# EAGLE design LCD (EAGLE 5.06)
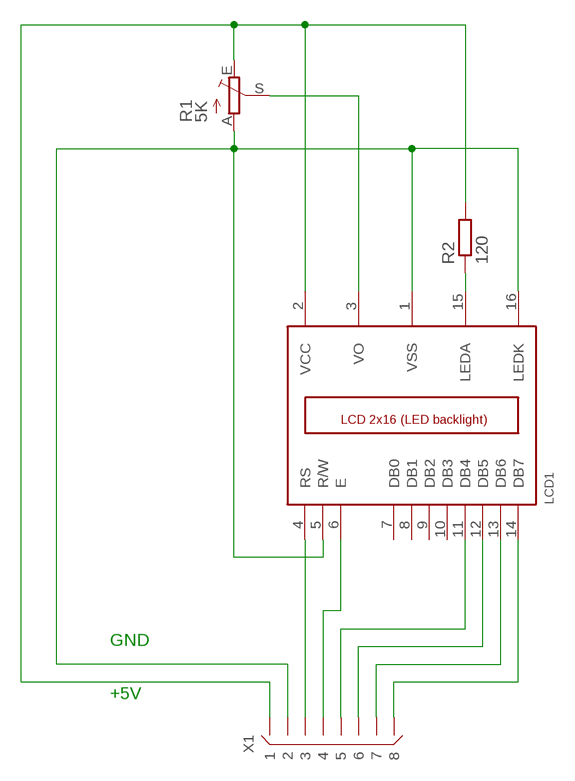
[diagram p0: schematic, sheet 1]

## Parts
LCD1  LCD_2X16  [HY-1602F]
R1  5K  TRIM_EU-CA6V  [CA6V]
R2  120  R-EU_0207/10  [0207/10]
X1  X08L  [X08L-SIL]

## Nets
N$1: LCD1.11(DB4) X1.5
N$2: LCD1.2(VCC) R1.E R2.2 X1.1
N$3: LCD1.3(VO) R1.S
N$4: LCD1.12(DB5) X1.6
N$5: LCD1.13(DB6) X1.7
N$6: LCD1.14(DB7) X1.8
N$7: LCD1.1(VSS) LCD1.5(R/W) LCD1.16(LEDK) R1.A X1.2
N$8: LCD1.4(RS) X1.3
N$10: LCD1.15(LEDA) R2.1
N$16: LCD1.6(E) X1.4
Unconnected: LCD1.7(DB0) LCD1.8(DB1) LCD1.9(DB2) LCD1.10(DB3)

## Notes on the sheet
- GND
- +5V

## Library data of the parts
LCD1 = lcd_2x16_led_backlight:LCD_2X16
R1 = pot:TRIM_EU-: POTENTIOMETER
R2 = resistor:R-EU_: RESISTOR, European symbol
X1 = connectors:X08: Connector 8 pins

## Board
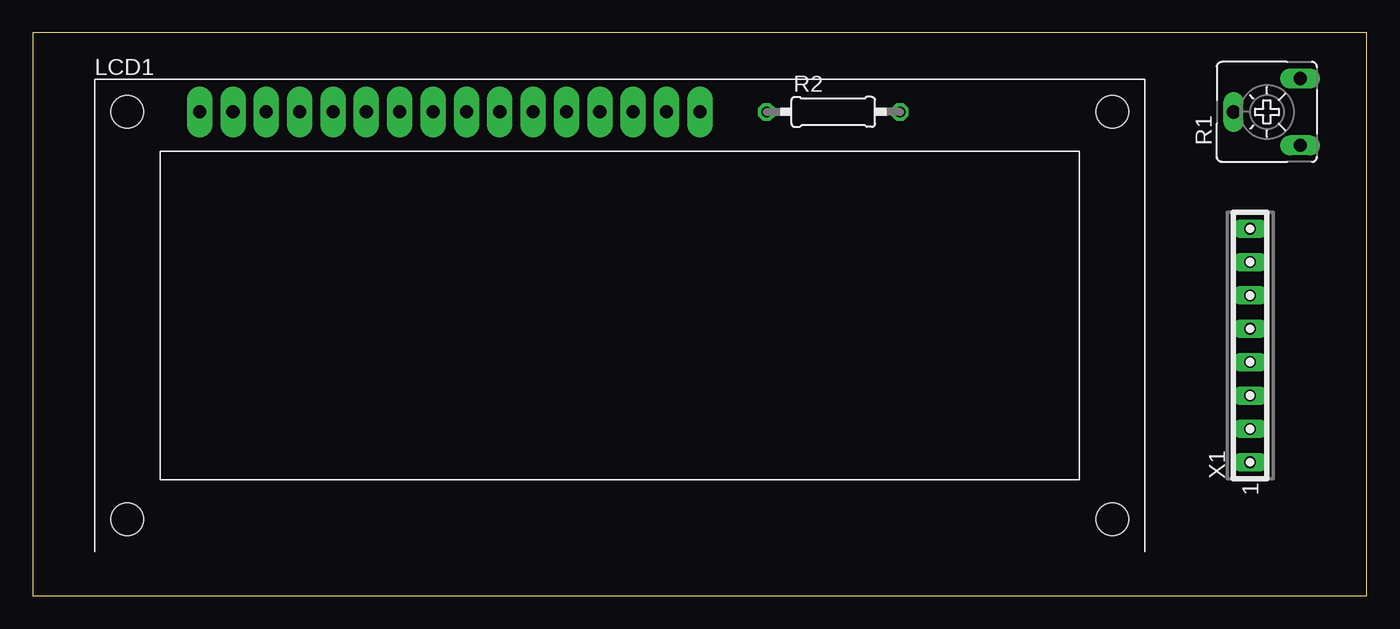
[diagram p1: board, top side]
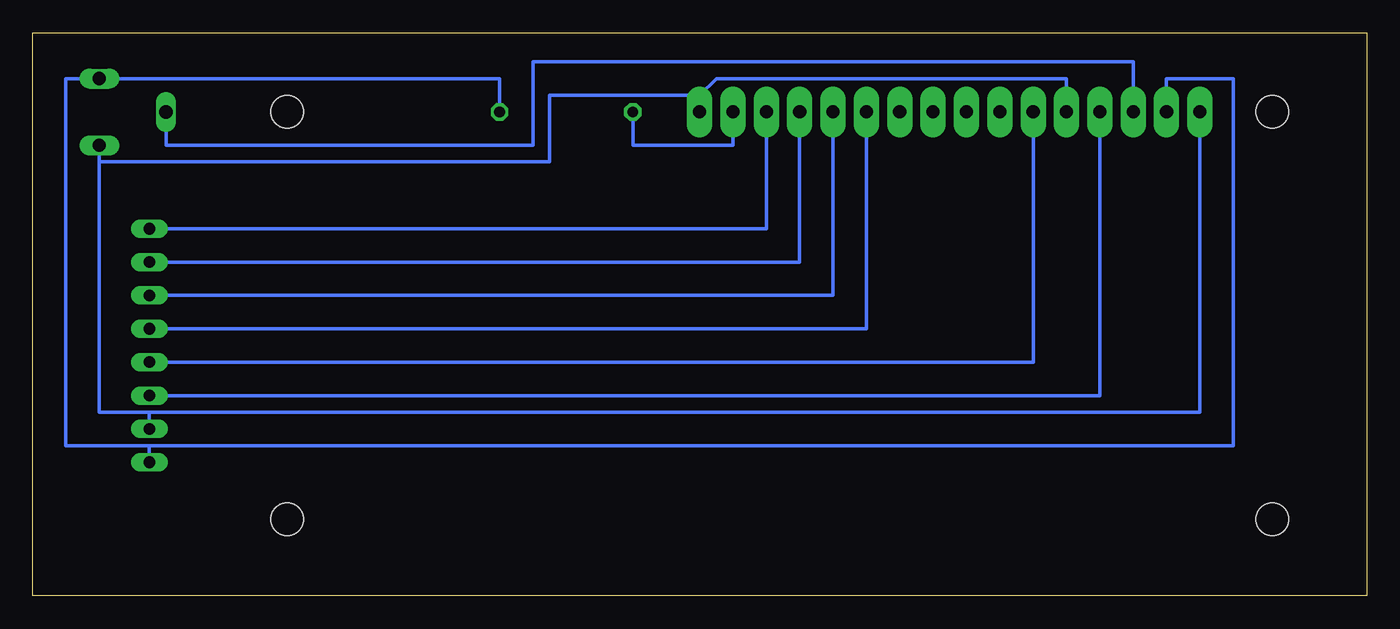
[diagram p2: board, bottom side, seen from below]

Size 101.58 x 42.85 mm. Coordinates in mm from the lower left corner, seen from the top.
Outline: 0,0 101.58,0 101.58,42.85 0,42.85 0,0
Copper layers (1*16): Top 0.035mm / dielectric 1.5mm / Bottom 0.035mm
Design rules "default": minimum track width 10mil, minimum drill 24mil, track to track 8mil, track to pad 8mil, pad to pad 8mil, via to via 8mil, smd to smd 8mil, copper to edge 40mil, drill to drill 8mil, minimum pad ring 10mil, minimum via ring 8mil, stop-mask expansion 4mil, vias tented up to drill 0mil, thermal gap 10mil

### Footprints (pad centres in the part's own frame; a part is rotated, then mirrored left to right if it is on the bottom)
HY-1602F = drill 1 pad 1.93 long: 1 2.54,0; 2 5.08,0; 3 7.62,0; 4 10.16,0; 5 12.7,0; 6 15.24,0; 7 17.78,0; 8 20.32,0; 9 22.86,0; 10 25.4,0; 11 27.94,0; 12 30.48,0; 13 33.02,0; 14 35.56,0; 15 38.1,0; 16 40.64,0 | hole 2.5: -2.96,0; 72.04,0; -2.96,-31; 72.04,-31
CA6V = drill 1.016 long: A -2.54,-2.54; E 2.54,-2.54; S 0,2.54
0207/10 = drill 0.813 octagon: 1 -5.08,0; 2 5.08,0
X08L-SIL = drill 0.889 pad 1.397 long: 1 -8.89,0; 2 -6.35,0; 3 -3.81,0; 4 -1.27,0; 5 1.27,0; 6 3.81,0; 7 6.35,0; 8 8.89,0

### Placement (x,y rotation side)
LCD1  10.16,36.83 0 top
R1  93.98,36.83 90 top
R2  60.96,36.83 0 top
X1  92.71,19.05 90 top

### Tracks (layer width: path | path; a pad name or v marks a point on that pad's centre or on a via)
N$1
  Bottom 0.254: X1.5 38.1,20.32 LCD1.11
N$2
  Bottom 0.254: R2.2 66.04,39.37 R1.E 99.06,39.37 99.06,11.43 92.71,11.43 | 92.71,11.43 X1.1 | LCD1.2 15.24,39.37 10.16,39.37 10.16,11.43 92.71,11.43
N$3
  Bottom 0.254: R1.S 91.44,34.29 63.5,34.29 63.5,40.64 17.78,40.64 LCD1.3
N$4
  Bottom 0.254: X1.6 40.64,22.86 LCD1.12
N$5
  Bottom 0.254: X1.7 43.18,25.4 LCD1.13
N$6
  Bottom 0.254: X1.8 45.72,27.94 LCD1.14
N$7
  Bottom 0.254: LCD1.5 22.86,39.37 49.53,39.37 50.8,38.1 | 92.71,13.97 96.52,13.97 96.52,33.02 | 92.71,13.97 X1.2 | 96.52,33.02 R1.A | LCD1.1 12.7,13.97 92.71,13.97 | 50.8,38.1 62.23,38.1 62.23,33.02 96.52,33.02 | 50.8,38.1 LCD1.16
N$8
  Bottom 0.254: X1.3 20.32,15.24 LCD1.4
N$10
  Bottom 0.254: R2.1 55.88,34.29 48.26,34.29 LCD1.15
N$16
  Bottom 0.254: X1.4 25.4,17.78 LCD1.6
